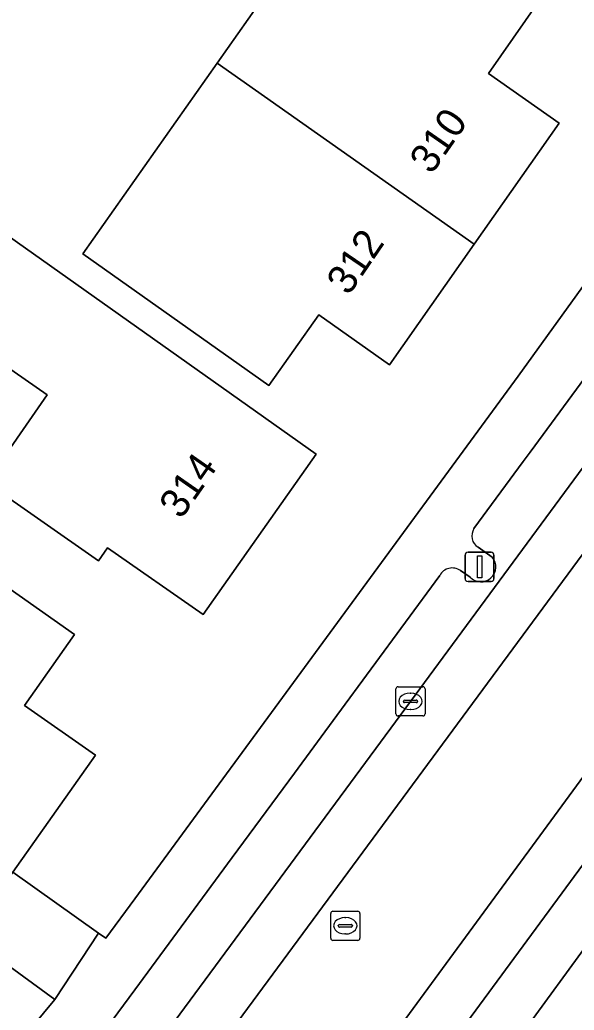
# Model space of a CAD drawing. Extents: x 160554 to 161248, y 385329 to 386506.
# Drawn here: x 160996.05 to 161015.07, y 386040.42 to 386074.38 of the extents above; entities that cross this region are included whole.
import ezdxf

# ---------------------------------------------------------------- set-up
doc = ezdxf.new("R2010")
doc.units = 0
for name, color, linetype in [('IMGEO_Erf', 7, 'Continuous'), ('IMGEO_Groenvoorziening', 7, 'Continuous'), ('IMGEO_Kolk', 7, 'Continuous'), ('IMGEO_Lichtmast', 7, 'Continuous'), ('IMGEO_Pand', 7, 'Continuous'), ('IMGEO_Pand_nummerreeks', 7, 'Continuous'), ('IMGEO_Parkeervlak_open', 7, 'Continuous'), ('IMGEO_Rijbaan_lokaal_gesloten', 7, 'Continuous'), ('IMGEO_Rioolput', 7, 'Continuous'), ('IMGEO_Voetpad_open', 7, 'Continuous')]:
    doc.layers.add(name, color=color, linetype=linetype)

msp = doc.modelspace()

# ---------------------------------------------------------------- linework, layer by layer
at = {"layer": 'IMGEO_Erf'}
for points in [[(160991.532, 386057.802), (160997.929, 386053.306), (160996.214, 386050.873), (160998.654, 386049.166), (160995.815, 386045.154), (160998.752, 386043.065), (160999.004, 386042.886), (161000, 386044.243), (161013.149, 386062.159), (161020.189, 386071.923), (161020.031, 386072.035), (161037.312, 386095.872)], [(160991.528, 386069.892), (161006.219, 386059.487), (161002.341, 386053.993), (160999.062, 386056.274), (160998.755, 386055.832), (160994.897, 386058.516), (160996.989, 386061.524), (160989.208, 386066.941)]]:
    msp.add_lwpolyline(points, dxfattribs=at)
msp.add_lwpolyline([(161002.826, 386072.899), (161007.433, 386079.446), (161013.819, 386074.966), (161012.127, 386072.54), (161014.552, 386070.835), (161011.64, 386066.694), (161008.729, 386062.553), (161006.307, 386064.263), (161004.597, 386061.839), (160998.218, 386066.352)], close=True, dxfattribs=at)
at = {"layer": 'IMGEO_Groenvoorziening'}
msp.add_lwpolyline([(160995.815, 386045.154), (160995.621, 386044.88), (160986.813, 386051.085), (160985.588, 386049.309), (160997.25, 386040.786), (160998.752, 386043.065)], close=True, dxfattribs=at)
at = {"layer": 'IMGEO_Kolk'}
for p, q in [((161008.952, 386050.583), (161008.952, 386051.435)), ((161009.027, 386051.509), (161009.879, 386051.509)), ((161009.953, 386051.435), (161009.953, 386050.583)), ((161009.254, 386051.052), (161009.652, 386051.052)), ((161009.44, 386051.289), (161009.465, 386051.289)), ((161009.211, 386051.003), (161009.211, 386051.015)), ((161009.649, 386050.966), (161009.251, 386050.966)), ((161009.463, 386050.729), (161009.438, 386050.729)), ((161009.695, 386051.015), (161009.695, 386051.003)), ((161009.879, 386050.509), (161009.027, 386050.509))]:
    msp.add_line(p, q, dxfattribs=at)
for points in [[(161008.952, 386050.583), (161008.952, 386051.435)], [(161009.027, 386051.509), (161009.879, 386051.509)], [(161009.953, 386051.435), (161009.953, 386050.583)], [(161009.879, 386050.509), (161009.027, 386050.509)]]:
    msp.add_lwpolyline(points, dxfattribs=at)
for centre, radius, start, end in [((161009.029, 386051.433), 0.0765, 91.552, 178.448), ((161009.029, 386051.433), 0.0765, 91.552, 178.448), ((161009.877, 386051.433), 0.0765, 1.552, 88.448), ((161009.877, 386051.433), 0.0765, 1.552, 88.448), ((161009.251, 386051.012), 0.0403, 85.8775, 175.7526), ((161009.656, 386051.014), 0.0386, 1.7309, 96.639), ((161009.248, 386051.002), 0.0366, 178.938, 274.7102), ((161009.652, 386051.009), 0.043, 264.8664, 352.4533), ((161009.029, 386050.585), 0.0765, 181.552, 268.448), ((161009.029, 386050.585), 0.0765, 181.552, 268.448), ((161009.877, 386050.585), 0.0765, 271.552, 358.448), ((161009.877, 386050.585), 0.0765, 271.552, 358.448)]:
    msp.add_arc(centre, radius, start, end, dxfattribs=at)
for centre, major_axis, ratio, start_param, end_param in [((161009.439, 386051.009), (-0.387, 0.002), 0.722429, 4.712389, 7.853982), ((161009.464, 386051.009), (-0.39, 0.002), 0.717154, 1.570796, 4.712389)]:
    msp.add_ellipse(centre, major_axis=major_axis, ratio=ratio, start_param=start_param, end_param=end_param, dxfattribs=at)
at = {"layer": 'IMGEO_Lichtmast'}
for p, q in [((161011.426, 386056.121), (161012.216, 386056.121)), ((161012.216, 386056.121), (161011.426, 386056.121)), ((161011.326, 386055.221), (161011.326, 386056.021)), ((161011.326, 386056.021), (161011.326, 386055.221)), ((161012.316, 386056.021), (161012.316, 386055.221)), ((161012.316, 386055.221), (161012.316, 386056.021)), ((161012.216, 386055.121), (161011.426, 386055.121)), ((161011.426, 386055.121), (161012.216, 386055.121))]:
    msp.add_line(p, q, dxfattribs=at)
msp.add_lwpolyline([(161011.746, 386055.996), (161011.896, 386055.996), (161011.896, 386055.246), (161011.746, 386055.246), (161011.746, 386055.996)], dxfattribs=at)
for centre, start, end in [((161011.426, 386056.021), 90, 180), ((161011.426, 386056.021), 90, 180), ((161012.216, 386056.021), 0, 90), ((161012.216, 386056.021), 360, 90), ((161011.426, 386055.221), 180, 270), ((161011.426, 386055.221), 180, 270), ((161012.216, 386055.221), 270, 0), ((161012.216, 386055.221), 270, 0)]:
    msp.add_arc(centre, 0.1, start, end, dxfattribs=at)
at = {"layer": 'IMGEO_Pand'}
for points in [[(161014.552, 386070.835), (161012.127, 386072.54), (161013.819, 386074.966), (161007.433, 386079.446), (161002.826, 386072.899), (161011.64, 386066.694)], [(160998.218, 386066.352), (161004.597, 386061.839), (161006.307, 386064.263), (161008.729, 386062.553), (161011.64, 386066.694), (161002.826, 386072.899)], [(160995.621, 386044.88), (160995.815, 386045.154), (160998.654, 386049.166), (160996.214, 386050.873), (160997.929, 386053.306), (160991.532, 386057.802), (160986.813, 386051.085)]]:
    msp.add_lwpolyline(points, close=True, dxfattribs=at)
msp.add_lwpolyline([(160989.208, 386066.941), (160996.989, 386061.524), (160994.897, 386058.516), (160998.755, 386055.832), (160999.062, 386056.274), (161002.341, 386053.993), (161006.219, 386059.487), (160991.528, 386069.892)], dxfattribs=at)
at = {"layer": 'IMGEO_Parkeervlak_open'}
for points in [[(160976.652, 386009.373), (160975.11, 386007.27), (160972.858, 386004.232), (160970.204, 386000.616), (160971.032, 386000), (160971.643, 385999.545), (160971.97, 386000), (160972.852, 386001.227), (160983.563, 386015.786), (160998.174, 386035.721), (161000, 386038.196), (161009.453, 386051.008), (161021.653, 386067.561), (161023.371, 386069.875), (161021.906, 386070.95), (161021.375, 386070.218), (161019.305, 386067.366), (161019.153, 386067.159), (161013.554, 386059.558), (161013.312, 386059.23), (161011.63, 386056.933)], [(161011.77, 386056.293), (161012.254, 386055.955)], [(161011.499, 386055.264), (161011.163, 386055.498)], [(161010.457, 386055.331), (161006.926, 386050.524), (161005.473, 386048.546), (161003.342, 386045.656), (161000, 386041.122), (160998.831, 386039.536), (160996.275, 386036.02)]]:
    msp.add_lwpolyline(points, dxfattribs=at)
msp.add_lwpolyline([(161010.768, 386036.201), (161013.44, 386039.843), (161017.583, 386045.505), (161031.343, 386064.18), (161029.852, 386065.192), (161027.941, 386062.559), (161016.115, 386046.431), (161004.434, 386030.555), (161000, 386024.524), (160990.279, 386011.323), (160981.972, 386000), (160979.051, 385996.019), (160978.106, 385994.757), (160979.543, 385993.676), (160982.2, 385997.316), (160984.169, 386000), (160985.764, 386002.174), (160990.8, 386009.037), (160993.034, 386012.051), (161000, 386021.52), (161004.076, 386027.06), (161005.853, 386029.488)], close=True, dxfattribs=at)
for centre, radius, start, end in [((161012.019, 386056.683), 0.462, 147.2071, 237.4711), ((161011.867, 386055.62), 0.512, 223.992, 40.9395), ((161010.885, 386055.097), 0.488, 55.2333, 151.3834)]:
    msp.add_arc(centre, radius, start, end, dxfattribs=at)
at = {"layer": 'IMGEO_Rijbaan_lokaal_gesloten'}
for points in [[(160999.584, 386034.684), (161024.79, 386068.85), (161023.371, 386069.875), (161021.653, 386067.561), (161009.453, 386051.008), (161000, 386038.196), (160998.174, 386035.721), (160983.563, 386015.786), (160972.852, 386001.227), (160971.97, 386000), (160971.643, 385999.545), (160972.908, 385998.607)], [(161028.434, 386066.217), (161024.79, 386068.85), (160999.584, 386034.684), (160972.908, 385998.607), (160976.7, 385995.799), (161003.024, 386031.591)], [(160976.7, 385995.799), (160978.106, 385994.757), (160979.051, 385996.019), (160981.972, 386000), (160990.279, 386011.323), (161000, 386024.524), (161004.434, 386030.555), (161016.115, 386046.431), (161027.941, 386062.559), (161029.852, 386065.192), (161028.434, 386066.217), (161003.024, 386031.591)]]:
    msp.add_lwpolyline(points, close=True, dxfattribs=at)
at = {"layer": 'IMGEO_Rioolput'}
for p, q in [((161006.718, 386042.888), (161006.718, 386043.74)), ((161006.793, 386043.814), (161007.645, 386043.814)), ((161007.206, 386043.594), (161007.231, 386043.594)), ((161007.719, 386043.74), (161007.719, 386042.888)), ((161006.977, 386043.308), (161006.977, 386043.32)), ((161007.415, 386043.271), (161007.017, 386043.271)), ((161007.02, 386043.357), (161007.418, 386043.357)), ((161007.461, 386043.32), (161007.461, 386043.308)), ((161007.229, 386043.034), (161007.204, 386043.034)), ((161007.645, 386042.814), (161006.793, 386042.814))]:
    msp.add_line(p, q, dxfattribs=at)
for points in [[(161006.718, 386042.888), (161006.718, 386043.74)], [(161006.793, 386043.814), (161007.645, 386043.814)], [(161007.719, 386043.74), (161007.719, 386042.888)], [(161007.645, 386042.814), (161006.793, 386042.814)]]:
    msp.add_lwpolyline(points, dxfattribs=at)
for centre, radius, start, end in [((161006.795, 386043.738), 0.0765, 91.552, 178.448), ((161006.795, 386043.738), 0.0765, 91.552, 178.448), ((161007.643, 386043.738), 0.0765, 1.552, 88.448), ((161007.643, 386043.738), 0.0765, 1.552, 88.448), ((161007.017, 386043.317), 0.0403, 85.8775, 175.7526), ((161007.014, 386043.307), 0.0366, 178.938, 274.7102), ((161007.418, 386043.314), 0.043, 264.8664, 352.4533), ((161007.422, 386043.319), 0.0386, 1.7309, 96.639), ((161006.795, 386042.89), 0.0765, 181.552, 268.448), ((161006.795, 386042.89), 0.0765, 181.552, 268.448), ((161007.643, 386042.89), 0.0765, 271.552, 358.448), ((161007.643, 386042.89), 0.0765, 271.552, 358.448)]:
    msp.add_arc(centre, radius, start, end, dxfattribs=at)
for centre, major_axis, ratio, start_param, end_param in [((161007.205, 386043.314), (-0.387, 0.002), 0.722429, 4.712389, 7.853982), ((161007.23, 386043.314), (-0.39, 0.002), 0.717154, 1.570796, 4.712389)]:
    msp.add_ellipse(centre, major_axis=major_axis, ratio=ratio, start_param=start_param, end_param=end_param, dxfattribs=at)
at = {"layer": 'IMGEO_Voetpad_open'}
for points in [[(161073.083, 386139.837), (161070.533, 386139.935), (161037.312, 386095.872), (161020.031, 386072.035), (161020.189, 386071.923), (161013.149, 386062.159), (161000, 386044.243), (160999.004, 386042.886), (160998.752, 386043.065), (160997.25, 386040.786), (160995.645, 386038.84), (160967.525, 386000), (160959.183, 385988.478), (160961.602, 385988.896), (160965.158, 385993.757), (160969.751, 386000), (160970.204, 386000.616), (160972.858, 386004.232), (160975.11, 386007.27), (160976.652, 386009.373)], [(161011.63, 386056.933), (161013.312, 386059.23), (161013.554, 386059.558), (161019.153, 386067.159), (161019.305, 386067.366), (161021.375, 386070.218), (161021.906, 386070.95), (161027.072, 386077.956), (161030.41, 386082.466)], [(161040.201, 386076.234), (161036.354, 386070.977), (161031.343, 386064.18), (161017.583, 386045.505), (161013.44, 386039.843), (161010.768, 386036.201), (161005.853, 386029.488), (161004.076, 386027.06), (161000, 386021.52), (160993.034, 386012.051), (160990.8, 386009.037), (160985.764, 386002.174), (160984.169, 386000), (160982.2, 385997.316), (160979.543, 385993.676), (160974.499, 385986.822), (160971.075, 385982.159), (160970.405, 385981.766), (160969.13, 385981.559)], [(160949.326, 386072.761), (160995.645, 386038.84), (160997.25, 386040.786), (160985.588, 386049.309)], [(161012.254, 386055.955), (161011.77, 386056.293)], [(161011.163, 386055.498), (161011.499, 386055.264)], [(160996.275, 386036.02), (160998.831, 386039.536), (161000, 386041.122), (161003.342, 386045.656), (161005.473, 386048.546), (161006.926, 386050.524), (161010.457, 386055.331)]]:
    msp.add_lwpolyline(points, dxfattribs=at)
for centre, radius, start, end in [((161012.019, 386056.683), 0.462, 147.2071, 237.4711), ((161011.867, 386055.62), 0.512, 223.992, 40.9395), ((161010.885, 386055.097), 0.488, 55.2333, 151.3834)]:
    msp.add_arc(centre, radius, start, end, dxfattribs=at)

# ---------------------------------------------------------------- texts
at = {"layer": 'IMGEO_Pand_nummerreeks'}
for s, rotation, p in [('310', 55.2665, (161010.176, 386069.048)), ('312', 55.6945, (161007.333, 386064.895)), ('314', 55.1816, (161001.587, 386057.224))]:
    msp.add_text(s, height=1, rotation=rotation, dxfattribs=at).set_placement(p)

doc.saveas('drawing.dxf')
